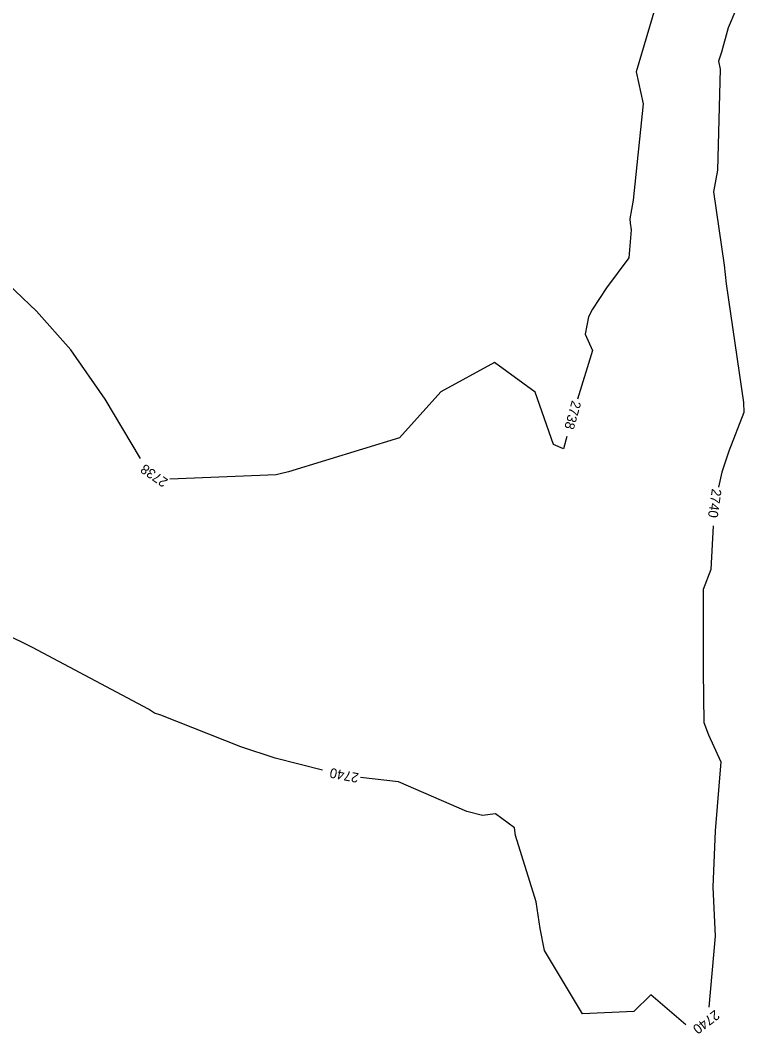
# Model space of a CAD drawing. Extents: x 1326424 to 1329294, y 1001359 to 1003823.
# Drawn here: x 1327963.8 to 1328112.3, y 1001925 to 1002132.9 of the extents above; entities that cross this region are included whole.
import ezdxf

# ---------------------------------------------------------------- set-up
doc = ezdxf.new("R2010")
doc.units = 0
doc.layers.add('Prop Rem of Exist Asph Pvmt', color=7, linetype='Continuous')
doc.layers.add('Scratch_Level_3', color=7, linetype='Continuous')

msp = doc.modelspace()

# ---------------------------------------------------------------- linework, layer by layer
at = {"layer": 'Prop Rem of Exist Asph Pvmt'}
for points in [[(1328110.61, 1002135.08), (1328109.05, 1002131.38), (1328107.66, 1002126.41), (1328107.1, 1002124.52), (1328107.44, 1002122.93), (1328106.9, 1002102.21), (1328106.04, 1002097.76), (1328108.22, 1002082.7), (1328108.65, 1002078.85), (1328112.24, 1002054.51), (1328112.26, 1002052.45), (1328109.23, 1002044.54), (1328107.76, 1002040.24), (1328107.08, 1002037.12)], [(1328105.96, 1002029.22), (1328105.49, 1002020.22), (1328103.93, 1002016.15), (1328103.92, 1001999.34), (1328104.06, 1001988.81), (1328105.04, 1001986.33), (1328107.57, 1001980.79), (1328106.4, 1001966.59), (1328105.93, 1001955.07), (1328106.36, 1001945), (1328105.09, 1001930.39)], [(1328025.79, 1001979.07), (1328016.11, 1001981.49), (1328009.07, 1001983.82), (1327992.62, 1001990.33), (1327991.34, 1001990.74), (1327990.09, 1001991.57), (1327966.28, 1002004.24), (1327960.37, 1002007.16), (1327943.04, 1002009.7), (1327940.17, 1002012.18), (1327932.97, 1002011.99)], [(1328100.36, 1001926.78), (1328093.21, 1001932.92), (1328089.71, 1001929.5), (1328079.14, 1001929.03), (1328071.35, 1001942.03), (1328070.49, 1001946.56), (1328069.67, 1001952.03), (1328065.41, 1001965.68), (1328065.22, 1001967.19), (1328061.29, 1001970.08), (1328058.62, 1001969.74), (1328055.45, 1001970.55), (1328041.42, 1001976.64), (1328033.62, 1001977.54)]]:
    msp.add_lwpolyline(points, dxfattribs=at)
at = {"layer": 'Scratch_Level_3'}
for points in [[(1328097.64, 1002150.42), (1328096.55, 1002144.27), (1328095.09, 1002139.04), (1328090.18, 1002122.39), (1328091.59, 1002115.79), (1328089.59, 1002096.03), (1328088.85, 1002092.22), (1328088.98, 1002091.29), (1328089.13, 1002089.97), (1328088.68, 1002084.16), (1328084.06, 1002078.04), (1328081.21, 1002073.63), (1328080.41, 1002072.06), (1328079.75, 1002068.56), (1328081.21, 1002065.21), (1328078.11, 1002055.2)], [(1327988.44, 1002042.98), (1327981.21, 1002055.2), (1327974.15, 1002065.32), (1327967.11, 1002073.28), (1327954.15, 1002085.58), (1327956.15, 1002094.31), (1327951.43, 1002102.33), (1327946.39, 1002106.53), (1327939.87, 1002113.2), (1327935.29, 1002113.74), (1327932.9, 1002116.12), (1327930.27, 1002117.19)], [(1328075.97, 1002047.5), (1328075.28, 1002045.01), (1328073.21, 1002045.9), (1328069.46, 1002056.63), (1328061.12, 1002062.7), (1328050.13, 1002056.69), (1328041.6, 1002047.25), (1328018.87, 1002040.3), (1328016.84, 1002039.82), (1328016.33, 1002039.68), (1327994.51, 1002038.8)]]:
    msp.add_lwpolyline(points, dxfattribs=at)

# ---------------------------------------------------------------- texts
at = {"layer": 'Prop Rem of Exist Asph Pvmt'}
for rotation, p in [(261.9581, (1328105.74, 1002036.9)), (169.0053, (1328033.37, 1001978.39)), (217.3481, (1328106.34, 1001929.94))]:
    msp.add_text('2740', height=2, rotation=rotation, dxfattribs=at).set_placement(p)
at = {"layer": 'Scratch_Level_3'}
for rotation, p in [(254.4748, (1328077.01, 1002055.04)), (145.4762, (1327994.26, 1002038.62))]:
    msp.add_text('2738', height=2, rotation=rotation, dxfattribs=at).set_placement(p)

doc.saveas('drawing.dxf')
